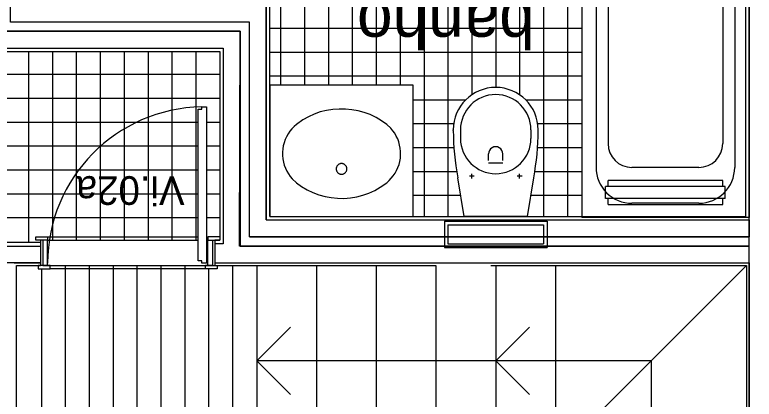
# Model space of a CAD drawing. Extents: x 1278 to 1356, y -253.7 to -224.
# Drawn here: x 1331.53 to 1334.624, y -240.985 to -239.375 of the extents above; entities that cross this region are included whole.
import ezdxf

# ---------------------------------------------------------------- set-up
doc = ezdxf.new("R2010")
doc.units = 0
for name, color, linetype in [('Level 1', 7, 'Continuous'), ('Level 10', 7, 'Continuous'), ('Level 11', 7, 'Continuous'), ('Level 13', 7, 'Continuous'), ('Level 2', 7, 'Continuous'), ('Level 4', 7, 'Continuous'), ('Level 40', 7, 'Continuous'), ('Level 60', 7, 'Continuous'), ('Level 65', 7, 'Continuous'), ('Level 66', 7, 'Continuous'), ('Level 67', 7, 'Continuous')]:
    doc.layers.add(name, color=color, linetype=linetype)

msp = doc.modelspace()

# ---------------------------------------------------------------- linework, layer by layer
at = {"layer": 'Level 1'}
for p, q in [((1334.6025, -240.234), (1334.6025, -238.614)), ((1332.5825, -240.234), (1332.5825, -239.3357)), ((1332.5125, -239.4057), (1331.5125, -239.4057)), ((1332.5125, -240.304), (1332.5125, -239.4057)), ((1331.4725, -239.444), (1332.4725, -239.444)), ((1332.4725, -239.444), (1332.4725, -240.344)), ((1331.4025, -239.514), (1332.4025, -239.514)), ((1332.4025, -239.514), (1332.4025, -240.334)), ((1331.6375, -240.319), (1331.6375, -240.424)), ((1332.3675, -240.319), (1332.3675, -240.424)), ((1332.4025, -240.334), (1332.3675, -240.334)), ((1332.4725, -240.344), (1334.6025, -240.344)), ((1331.5275, -240.414), (1331.6375, -240.414)), ((1332.3675, -240.414), (1334.6025, -240.414)), ((1334.6025, -240.414), (1334.6025, -242.034))]:
    msp.add_line(p, q, dxfattribs=at)
at = {"layer": 'Level 10'}
for p, q in [((1332.6425, -238.5207), (1332.6425, -239.669)), ((1332.7425, -238.5207), (1332.7425, -239.669)), ((1332.8425, -238.5207), (1332.8425, -239.669)), ((1332.9425, -238.5207), (1332.9425, -239.669)), ((1333.0425, -238.5207), (1333.0425, -239.669)), ((1333.1425, -238.629), (1333.1425, -239.669)), ((1333.2425, -238.629), (1333.2425, -240.219)), ((1333.3425, -238.629), (1333.3425, -240.219)), ((1333.7425, -238.629), (1333.7425, -240.219)), ((1333.8425, -238.629), (1333.8425, -240.219)), ((1333.4425, -239.1391), (1333.4425, -239.7067)), ((1333.6425, -239.1468), (1333.6425, -239.7067)), ((1333.5425, -239.1739), (1333.5425, -239.6759)), ((1332.5975, -239.4307), (1333.9025, -239.4307)), ((1331.5875, -239.529), (1331.5875, -240.329)), ((1331.6875, -239.529), (1331.6875, -240.319)), ((1331.7875, -239.529), (1331.7875, -240.319)), ((1331.8875, -239.529), (1331.8875, -240.319)), ((1331.9875, -239.529), (1331.9875, -240.319)), ((1332.0875, -239.529), (1332.0875, -240.319)), ((1332.1875, -239.529), (1332.1875, -240.319)), ((1332.2875, -239.529), (1332.2875, -240.319)), ((1332.5975, -239.5307), (1333.9025, -239.5307)), ((1330.1325, -239.624), (1332.3875, -239.624)), ((1332.5975, -239.6307), (1333.9025, -239.6307)), ((1330.6027, -239.724), (1332.3875, -239.724)), ((1333.1973, -239.7307), (1333.4142, -239.7307)), ((1333.6708, -239.7307), (1333.9025, -239.7307)), ((1330.6563, -239.824), (1332.2975, -239.824)), ((1332.3325, -239.824), (1332.3875, -239.824)), ((1333.1973, -239.8307), (1333.3665, -239.8307)), ((1333.7186, -239.8307), (1333.9025, -239.8307)), ((1330.6545, -239.924), (1332.2975, -239.924)), ((1332.3325, -239.924), (1332.3875, -239.924)), ((1333.1973, -239.9307), (1333.3676, -239.9307)), ((1333.7174, -239.9307), (1333.9025, -239.9307)), ((1330.6437, -240.024), (1332.2975, -240.024)), ((1332.3325, -240.024), (1332.3875, -240.024)), ((1333.1973, -240.0307), (1333.3795, -240.0307)), ((1333.7056, -240.0307), (1333.9025, -240.0307)), ((1330.6271, -240.124), (1332.2975, -240.124)), ((1332.3325, -240.124), (1332.3875, -240.124)), ((1333.1973, -240.1307), (1333.3962, -240.1307)), ((1333.6889, -240.1307), (1333.9025, -240.1307)), ((1330.8875, -240.224), (1332.2975, -240.224)), ((1332.3325, -240.224), (1332.3875, -240.224)), ((1331.6675, -240.319), (1332.2975, -240.319)), ((1331.6425, -243.129), (1331.6425, -240.439)), ((1331.6775, -240.424), (1332.3275, -240.424)), ((1331.7425, -243.129), (1331.7425, -240.424)), ((1331.8425, -243.129), (1331.8425, -240.424)), ((1331.9425, -243.129), (1331.9425, -240.424)), ((1332.0425, -243.129), (1332.0425, -240.424)), ((1332.1425, -243.129), (1332.1425, -240.424)), ((1332.2425, -243.129), (1332.2425, -240.424)), ((1332.3425, -243.129), (1332.3425, -240.439)), ((1332.4425, -242.194), (1332.4425, -240.424))]:
    msp.add_line(p, q, dxfattribs=at)
at = {"layer": 'Level 11'}
for p, q in [((1333.9025, -238.624), (1333.9025, -240.224)), ((1334.6025, -238.624), (1334.6025, -240.224)), ((1333.9625, -238.964), (1333.9625, -240.014)), ((1334.0125, -238.964), (1334.0125, -239.914)), ((1334.4925, -238.964), (1334.4925, -239.914)), ((1334.5425, -238.964), (1334.5425, -240.014)), ((1332.7832, -239.7905), (1332.7589, -239.8017)), ((1332.8084, -239.7816), (1332.7832, -239.7905)), ((1332.8344, -239.7759), (1332.8084, -239.7816)), ((1332.8607, -239.7715), (1332.8344, -239.7759)), ((1332.8873, -239.7694), (1332.8607, -239.7715)), ((1332.914, -239.7697), (1332.8873, -239.7694)), ((1332.9405, -239.7723), (1332.914, -239.7697)), ((1332.9669, -239.7763), (1332.9405, -239.7723)), ((1332.9926, -239.7835), (1332.9669, -239.7763)), ((1333.0176, -239.793), (1332.9926, -239.7835)), ((1333.0416, -239.8047), (1333.0176, -239.793)), ((1332.7357, -239.8149), (1332.7086, -239.8341)), ((1332.7589, -239.8017), (1332.7357, -239.8149)), ((1333.0646, -239.8184), (1333.0416, -239.8047)), ((1333.0863, -239.8341), (1333.0646, -239.8184)), ((1332.6893, -239.8524), (1332.6809, -239.8628)), ((1332.6986, -239.8428), (1332.6893, -239.8524)), ((1332.7086, -239.8341), (1332.6986, -239.8428)), ((1333.1035, -239.85), (1333.0863, -239.8341)), ((1333.1121, -239.8602), (1333.1035, -239.85)), ((1333.1198, -239.8711), (1333.1121, -239.8602)), ((1333.365, -239.8598), (1333.365, -239.8562)), ((1333.395, -239.8565), (1333.395, -239.8926)), ((1333.69, -239.8565), (1333.69, -239.8926)), ((1333.72, -239.8598), (1333.72, -239.8562)), ((1332.6669, -239.8855), (1332.6614, -239.8977)), ((1332.6734, -239.8738), (1332.6669, -239.8855)), ((1332.6809, -239.8628), (1332.6734, -239.8738)), ((1333.1266, -239.8827), (1333.1198, -239.8711)), ((1333.1323, -239.8948), (1333.1266, -239.8827)), ((1332.657, -239.9104), (1332.6537, -239.9234)), ((1332.6614, -239.8977), (1332.657, -239.9104)), ((1333.137, -239.9073), (1333.1323, -239.8948)), ((1333.1405, -239.9202), (1333.137, -239.9073)), ((1333.143, -239.9334), (1333.1405, -239.9202)), ((1332.6515, -239.9366), (1332.6505, -239.95)), ((1332.6505, -239.95), (1332.6506, -239.9638)), ((1332.6537, -239.9234), (1332.6515, -239.9366)), ((1333.1443, -239.9468), (1333.143, -239.9334)), ((1333.1444, -239.9606), (1333.1443, -239.9468)), ((1332.6506, -239.9638), (1332.6519, -239.9784)), ((1332.6519, -239.9784), (1332.6544, -239.9916)), ((1333.1412, -239.9885), (1333.1434, -239.9753)), ((1333.1434, -239.9753), (1333.1444, -239.9606)), ((1333.5125, -239.9845), (1333.5125, -239.9572)), ((1333.5725, -239.9845), (1333.5725, -239.9573)), ((1332.6544, -239.9916), (1332.6579, -240.0045)), ((1332.6579, -240.0045), (1332.6626, -240.0171)), ((1332.8759, -240.0143), (1332.8755, -240.0162)), ((1332.8765, -240.0124), (1332.8759, -240.0143)), ((1332.8772, -240.0106), (1332.8765, -240.0124)), ((1332.8781, -240.0089), (1332.8772, -240.0106)), ((1332.8792, -240.0072), (1332.8781, -240.0089)), ((1332.8804, -240.0057), (1332.8792, -240.0072)), ((1332.8817, -240.0042), (1332.8804, -240.0057)), ((1332.8831, -240.0029), (1332.8817, -240.0042)), ((1332.8847, -240.0017), (1332.8831, -240.0029)), ((1332.8863, -240.0006), (1332.8847, -240.0017)), ((1332.888, -239.9997), (1332.8863, -240.0006)), ((1332.8898, -239.999), (1332.888, -239.9997)), ((1332.8917, -239.9984), (1332.8898, -239.999)), ((1332.8936, -239.9979), (1332.8917, -239.9984)), ((1332.8955, -239.9977), (1332.8936, -239.9979)), ((1332.8975, -239.9976), (1332.8955, -239.9977)), ((1332.8994, -239.9977), (1332.8975, -239.9976)), ((1332.9013, -239.9979), (1332.8994, -239.9977)), ((1332.9032, -239.9984), (1332.9013, -239.9979)), ((1332.9051, -239.999), (1332.9032, -239.9984)), ((1332.9069, -239.9997), (1332.9051, -239.999)), ((1332.9086, -240.0006), (1332.9069, -239.9997)), ((1332.9102, -240.0017), (1332.9086, -240.0006)), ((1332.9118, -240.0029), (1332.9102, -240.0017)), ((1332.9132, -240.0042), (1332.9118, -240.0029)), ((1332.9145, -240.0057), (1332.9132, -240.0042)), ((1332.9157, -240.0072), (1332.9145, -240.0057)), ((1332.9168, -240.0089), (1332.9157, -240.0072)), ((1332.9177, -240.0106), (1332.9168, -240.0089)), ((1332.9184, -240.0124), (1332.9177, -240.0106)), ((1332.919, -240.0143), (1332.9184, -240.0124)), ((1332.9194, -240.0162), (1332.919, -240.0143)), ((1333.128, -240.0263), (1333.1335, -240.0141)), ((1333.1335, -240.0141), (1333.1379, -240.0015)), ((1333.1379, -240.0015), (1333.1412, -239.9885)), ((1333.5725, -239.9968), (1333.5125, -239.9968)), ((1334.3925, -240.014), (1334.1125, -240.014)), ((1332.6626, -240.0171), (1332.6683, -240.0292)), ((1332.6683, -240.0292), (1332.6751, -240.0407)), ((1332.6751, -240.0407), (1332.6828, -240.0516)), ((1332.8752, -240.0182), (1332.8751, -240.0202)), ((1332.8751, -240.0202), (1332.8752, -240.0221)), ((1332.8755, -240.0162), (1332.8752, -240.0182)), ((1332.8752, -240.0221), (1332.8755, -240.0241)), ((1332.8755, -240.0241), (1332.8759, -240.026)), ((1332.8759, -240.026), (1332.8765, -240.0279)), ((1332.8765, -240.0279), (1332.8772, -240.0297)), ((1332.8772, -240.0297), (1332.8781, -240.0314)), ((1332.8781, -240.0314), (1332.8792, -240.0331)), ((1332.8792, -240.0331), (1332.8804, -240.0347)), ((1332.8804, -240.0347), (1332.8817, -240.0361)), ((1332.8817, -240.0361), (1332.8831, -240.0374)), ((1332.8831, -240.0374), (1332.8847, -240.0386)), ((1332.8847, -240.0386), (1332.8863, -240.0397)), ((1332.8863, -240.0397), (1332.888, -240.0406)), ((1332.888, -240.0406), (1332.8898, -240.0414)), ((1332.8898, -240.0414), (1332.8917, -240.042)), ((1332.8917, -240.042), (1332.8936, -240.0424)), ((1332.8936, -240.0424), (1332.8955, -240.0426)), ((1332.8955, -240.0426), (1332.8975, -240.0427)), ((1332.8975, -240.0427), (1332.8994, -240.0426)), ((1332.8994, -240.0426), (1332.9013, -240.0424)), ((1332.9013, -240.0424), (1332.9032, -240.042)), ((1332.9032, -240.042), (1332.9051, -240.0414)), ((1332.9051, -240.0414), (1332.9069, -240.0406)), ((1332.9069, -240.0406), (1332.9086, -240.0397)), ((1332.9086, -240.0397), (1332.9102, -240.0386)), ((1332.9102, -240.0386), (1332.9118, -240.0374)), ((1332.9118, -240.0374), (1332.9132, -240.0361)), ((1332.9132, -240.0361), (1332.9145, -240.0347)), ((1332.9145, -240.0347), (1332.9157, -240.0331)), ((1332.9157, -240.0331), (1332.9168, -240.0314)), ((1332.9168, -240.0314), (1332.9177, -240.0297)), ((1332.9177, -240.0297), (1332.9184, -240.0279)), ((1332.9184, -240.0279), (1332.919, -240.026)), ((1332.919, -240.026), (1332.9194, -240.0241)), ((1332.9197, -240.0182), (1332.9194, -240.0162)), ((1332.9194, -240.0241), (1332.9197, -240.0221)), ((1332.9198, -240.0202), (1332.9197, -240.0182)), ((1332.9197, -240.0221), (1332.9198, -240.0202)), ((1333.114, -240.0491), (1333.1215, -240.038)), ((1333.1215, -240.038), (1333.128, -240.0263)), ((1333.4425, -240.0608), (1333.4425, -240.0408)), ((1333.6425, -240.0608), (1333.6425, -240.0408)), ((1332.6828, -240.0516), (1332.6914, -240.0618)), ((1332.6914, -240.0618), (1332.7086, -240.0778)), ((1333.0863, -240.0778), (1333.0963, -240.069)), ((1333.0963, -240.069), (1333.1056, -240.0595)), ((1333.1056, -240.0595), (1333.114, -240.0491)), ((1333.4102, -240.219), (1333.3836, -240.0569)), ((1333.4525, -240.0508), (1333.4325, -240.0508)), ((1333.6525, -240.0508), (1333.6325, -240.0508)), ((1333.6749, -240.219), (1333.7015, -240.0569)), ((1332.7086, -240.0778), (1332.7303, -240.0935)), ((1332.7303, -240.0935), (1332.7533, -240.1072)), ((1332.7533, -240.1072), (1332.7773, -240.1189)), ((1333.036, -240.1102), (1333.0592, -240.0969)), ((1333.0592, -240.0969), (1333.0863, -240.0778)), ((1332.7773, -240.1189), (1332.8023, -240.1284)), ((1332.8023, -240.1284), (1332.8282, -240.1356)), ((1332.8282, -240.1356), (1332.8544, -240.1406)), ((1332.9342, -240.1414), (1332.9607, -240.137)), ((1332.9607, -240.137), (1332.9865, -240.1303)), ((1332.9865, -240.1303), (1333.0117, -240.1213)), ((1333.0117, -240.1213), (1333.036, -240.1102)), ((1332.8544, -240.1406), (1332.8809, -240.1432)), ((1332.8809, -240.1432), (1332.9076, -240.1435)), ((1332.9076, -240.1435), (1332.9342, -240.1414)), ((1334.3925, -240.164), (1334.1125, -240.164)), ((1333.6749, -240.219), (1333.4102, -240.219)), ((1334.6025, -240.224), (1333.9025, -240.224)), ((1333.3275, -240.239), (1333.3275, -240.349)), ((1333.3275, -240.239), (1333.7575, -240.239)), ((1333.3425, -240.254), (1333.7425, -240.254)), ((1333.3425, -240.254), (1333.3425, -240.334)), ((1333.7425, -240.254), (1333.7425, -240.334)), ((1333.7575, -240.239), (1333.7575, -240.349)), ((1333.3275, -240.349), (1333.7575, -240.349)), ((1333.3425, -240.334), (1333.7425, -240.334))]:
    msp.add_line(p, q, dxfattribs=at)
for centre, radius, start, end in [((1333.5425, -239.8565), 0.1775, 0.0002, 179.9999), ((1333.5425, -239.8565), 0.1475, 0.0002, 179.9999), ((1333.5425, -239.8926), 0.1475, 180.0002, 359.9999), ((1334.1125, -239.914), 0.1, 180.0001, 269.9999), ((1334.3925, -239.914), 0.1, 270, 0), ((1333.5425, -239.9574), 0.03, 359.9995, 180.0013), ((1334.1125, -240.014), 0.15, 179.9998, 270.0001), ((1334.3925, -240.014), 0.15, 270, 0)]:
    msp.add_arc(centre, radius, start, end, dxfattribs=at)
for centre, major_axis, start_param, end_param in [((1334.765, -239.8598), (-1.4, 0), 6.283184, 6.446103), ((1332.32, -239.8598), (1.4, 0), 6.120269, 6.283188)]:
    msp.add_ellipse(centre, major_axis=major_axis, ratio=0.867931, start_param=start_param, end_param=end_param, dxfattribs=at)
at = {"layer": 'Level 13'}
for p, q in [((1332.3125, -239.7597), (1332.3325, -239.7597)), ((1332.3125, -239.7697), (1332.3125, -239.76)), ((1332.3325, -239.7597), (1332.3325, -240.4147)), ((1332.2975, -240.4047), (1332.2975, -239.7697)), ((1332.2975, -239.7697), (1332.3125, -239.7697)), ((1331.6175, -240.304), (1331.6675, -240.304)), ((1331.6175, -240.319), (1331.6175, -240.304)), ((1331.6675, -240.319), (1331.6175, -240.319)), ((1331.6475, -240.319), (1331.6475, -240.424)), ((1331.6675, -240.319), (1331.6475, -240.319)), ((1331.6675, -240.304), (1331.6675, -240.319)), ((1331.6675, -240.424), (1331.6675, -240.319)), ((1332.3875, -240.304), (1332.3375, -240.304)), ((1332.3375, -240.304), (1332.3375, -240.319)), ((1332.3375, -240.424), (1332.3375, -240.319)), ((1332.3375, -240.319), (1332.3575, -240.319)), ((1332.3375, -240.319), (1332.3875, -240.319)), ((1332.3575, -240.319), (1332.3575, -240.424)), ((1332.3125, -240.4047), (1332.2975, -240.4047)), ((1332.3125, -240.4147), (1332.3125, -240.4047)), ((1332.3325, -240.4147), (1332.3125, -240.4147)), ((1331.6775, -240.424), (1331.6275, -240.424)), ((1331.6275, -240.424), (1331.6275, -240.439)), ((1331.6275, -240.439), (1331.6775, -240.439)), ((1331.6475, -240.424), (1331.6775, -240.424)), ((1331.6775, -240.439), (1331.6775, -240.424)), ((1332.3575, -240.424), (1332.3275, -240.424)), ((1332.3275, -240.424), (1332.3775, -240.424)), ((1332.3275, -240.439), (1332.3275, -240.424)), ((1332.3775, -240.439), (1332.3275, -240.439)), ((1332.3775, -240.424), (1332.3775, -240.439))]:
    msp.add_line(p, q, dxfattribs=at)
at = {"layer": 'Level 2'}
for p, q in [((1333.1973, -239.669), (1332.5975, -239.669)), ((1332.5975, -239.669), (1332.5975, -240.219)), ((1333.1973, -240.219), (1333.1973, -239.669)), ((1332.5425, -240.424), (1332.5425, -241.194)), ((1332.7925, -240.424), (1332.7925, -241.194)), ((1333.0425, -240.424), (1333.0425, -241.194)), ((1333.2925, -240.424), (1333.2925, -241.194)), ((1333.5425, -240.424), (1333.5425, -241.194)), ((1333.7925, -240.424), (1333.7925, -241.194)), ((1333.7925, -241.224), (1334.5925, -240.424)), ((1333.7925, -240.424), (1333.7925, -241.194)), ((1332.6839, -240.6826), (1332.5425, -240.824)), ((1333.6839, -240.6826), (1333.5425, -240.824)), ((1332.6839, -240.9654), (1332.5425, -240.824)), ((1334.1925, -240.824), (1332.5425, -240.824)), ((1334.1925, -240.824), (1333.5425, -240.824)), ((1333.6839, -240.9654), (1333.5425, -240.824)), ((1334.1925, -240.824), (1334.1925, -241.624))]:
    msp.add_line(p, q, dxfattribs=at)
at = {"layer": 'Level 4'}
for p, q in [((1331.6675, -240.304), (1332.2975, -240.304)), ((1332.3275, -240.439), (1331.6775, -240.439))]:
    msp.add_line(p, q, dxfattribs=at)
msp.add_ellipse((1332.3262, -240.4147), major_axis=(0.6586, 0), ratio=0.994279, start_param=1.591512, end_param=3.141593, dxfattribs=at)
at = {"layer": 'Level 65'}
for p, q in [((1334.5875, -238.629), (1334.5875, -240.219)), ((1332.5975, -240.219), (1332.5975, -239.3207)), ((1331.3875, -239.529), (1332.3875, -239.529)), ((1332.3875, -239.529), (1332.3875, -240.319)), ((1332.5975, -240.219), (1334.5875, -240.219)), ((1332.3875, -240.319), (1332.3675, -240.319)), ((1331.6375, -240.329), (1330.8875, -240.329)), ((1331.5375, -242.194), (1331.5375, -240.424)), ((1331.5375, -240.424), (1331.6375, -240.424)), ((1332.3675, -240.424), (1333.2925, -240.424)), ((1333.5225, -240.424), (1334.5925, -240.424)), ((1334.5925, -240.424), (1334.5925, -242.024))]:
    msp.add_line(p, q, dxfattribs=at)
at = {"layer": 'Level 66'}
for p, q in [((1334.4925, -240.069), (1334.0125, -240.069)), ((1334.0125, -240.094), (1334.0125, -240.069)), ((1334.4925, -240.094), (1334.4925, -240.069)), ((1334.5025, -240.094), (1334.0025, -240.094)), ((1334.0025, -240.144), (1334.0025, -240.094)), ((1334.5025, -240.144), (1334.5025, -240.094)), ((1334.5025, -240.144), (1334.0025, -240.144)), ((1334.0125, -240.169), (1334.0125, -240.144)), ((1334.0125, -240.169), (1334.4925, -240.169)), ((1334.4925, -240.169), (1334.4925, -240.144)), ((1332.5825, -240.234), (1334.6025, -240.234)), ((1332.5125, -240.304), (1334.6025, -240.304)), ((1334.6025, -240.344), (1334.6025, -240.304)), ((1330.8725, -240.344), (1331.6375, -240.344))]:
    msp.add_line(p, q, dxfattribs=at)
at = {"layer": 'Level 67'}
for points in [[(1334.6025, -240.234), (1334.6025, -240.304), (1332.5125, -240.304), (1332.5125, -239.4057), (1331.5125, -239.4057), (1331.5125, -238.5057), (1330.3525, -238.5057), (1330.3525, -238.244), (1329.4325, -238.244), (1329.4325, -238.174), (1330.4233, -238.174), (1330.4233, -238.4357), (1331.4525, -238.4357), (1331.4525, -236.6557), (1331.5325, -236.6557), (1331.5325, -238.4357), (1331.6212, -238.4357), (1331.6175, -238.4357), (1331.6175, -238.5057), (1331.5825, -238.5057), (1331.5825, -239.3357), (1332.5825, -239.3357), (1332.5825, -240.234), (1334.6025, -240.234)], [(1334.6725, -242.1713), (1334.6025, -242.1713), (1334.6025, -242.104), (1332.5275, -242.104), (1332.5275, -242.194), (1332.4575, -242.194), (1332.4575, -242.034), (1334.6025, -242.034), (1334.6025, -236.7713), (1334.6725, -236.7713)], [(1334.6025, -240.344), (1332.4698, -240.344), (1332.4725, -239.444), (1331.4725, -239.444), (1331.4725, -238.544), (1329.4325, -238.544), (1329.4325, -238.614), (1331.4025, -238.614), (1331.4025, -239.514), (1332.4025, -239.514), (1332.4025, -240.334), (1332.3675, -240.334), (1332.3675, -240.414), (1334.6025, -240.414)], [(1331.6375, -240.344), (1331.6375, -240.414), (1330.4225, -240.414), (1330.4225, -240.344)]]:
    msp.add_lwpolyline(points, close=True, dxfattribs=at)

# ---------------------------------------------------------------- texts
at = {"layer": 'Level 40'}
msp.add_text('Vi.02a', height=0.12, rotation=180, dxfattribs=at).set_placement((1332.2405, -240.0507))
at = {"layer": 'Level 60'}
msp.add_text('banho', height=0.2, rotation=180, dxfattribs=at).set_placement((1333.7059, -239.3132))

doc.saveas('drawing.dxf')
